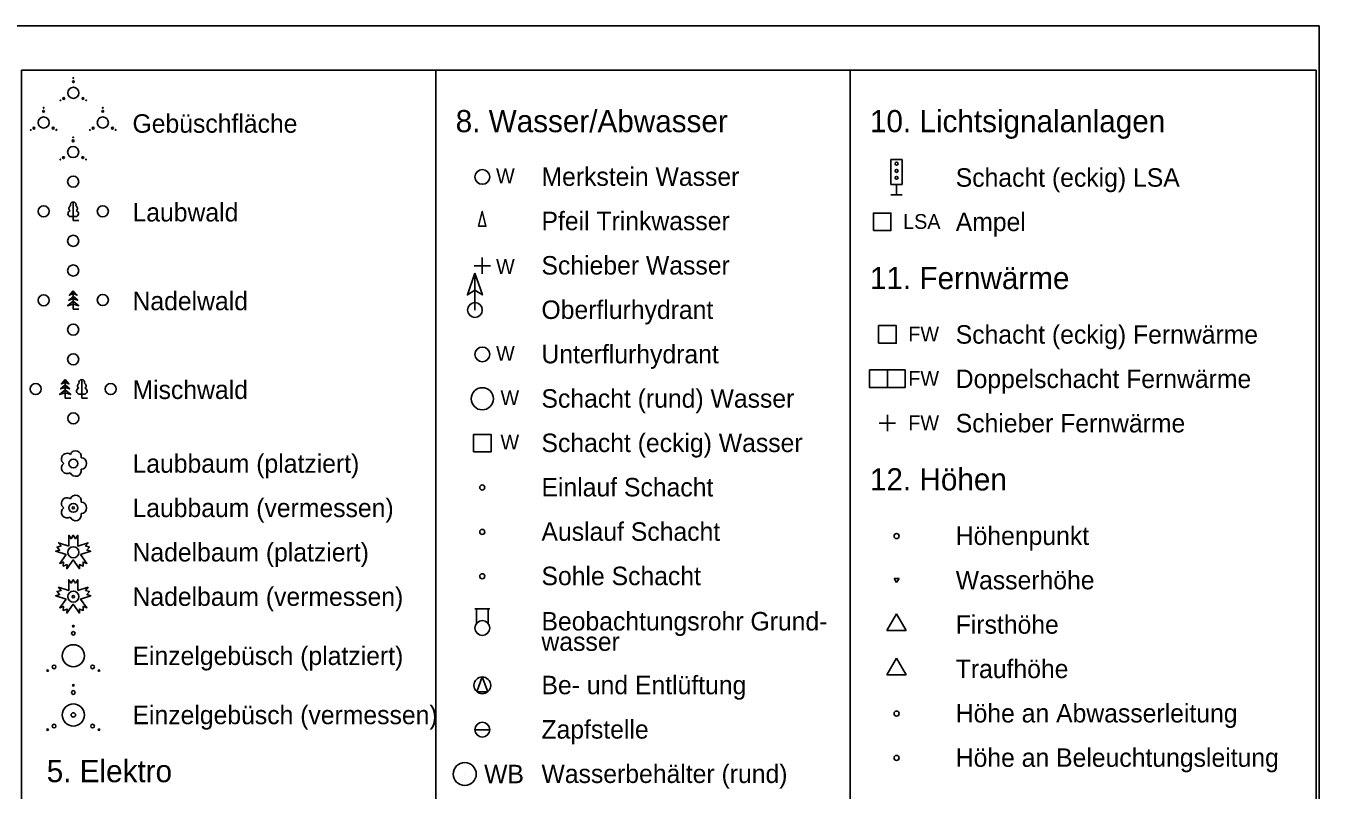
# Model space of a CAD drawing. Extents: x 679244 to 679420, y 5639809 to 5639932.
# Drawn here: x 679332.6 to 679420, y 5639880 to 5639931.7 of the extents above; entities that cross this region are included whole.
import ezdxf

# ---------------------------------------------------------------- set-up
doc = ezdxf.new("R2010")
doc.units = 0
for name, color, linetype in [('Ampel', 7, 'Continuous'), ('Auslauf_schacht', 7, 'Continuous'), ('Be_entlueftung', 7, 'Continuous'), ('Beobrohr_gw', 7, 'Continuous'), ('Busch_platz', 7, 'Continuous'), ('Busch_verm', 7, 'Continuous'), ('Default', 7, 'Continuous'), ('Doppelschacht_fw', 7, 'Continuous'), ('Einlauf_schacht', 7, 'Continuous'), ('Gebuesch', 7, 'Continuous'), ('Hoehe_aw_symbol', 7, 'Continuous'), ('Hoehe_bel_symbol', 7, 'Continuous'), ('Hoehe_first_symbol', 7, 'Continuous'), ('Hoehe_trauf_symbol', 7, 'Continuous'), ('Hoehe_wasser_symbol', 7, 'Continuous'), ('Hoehenpunkt_symbol', 7, 'Continuous'), ('Laubbaum', 7, 'Continuous'), ('Laubwald', 7, 'Continuous'), ('Merkstein_wasser', 7, 'Continuous'), ('Mischwald', 7, 'Continuous'), ('Nadelbaum', 7, 'Continuous'), ('Nadelwald', 7, 'Continuous'), ('Oberflurhydrant', 7, 'Continuous'), ('Pfeil_trinkwasser', 7, 'Continuous'), ('Rahmen_1', 7, 'Continuous'), ('Schacht_e_fw', 7, 'Continuous'), ('Schacht_e_lsa', 7, 'Continuous'), ('Schacht_e_wasser', 7, 'Continuous'), ('Schacht_r_wasser', 7, 'Continuous'), ('Schieber_fw', 7, 'Continuous'), ('Schieber_wasser', 7, 'Continuous'), ('Schrift_fw', 7, 'Continuous'), ('Schrift_lsa', 7, 'Continuous'), ('Schrift_w', 7, 'Continuous'), ('Schrift_wb', 7, 'Continuous'), ('Sohle_schacht', 7, 'Continuous'), ('Unterflurhydrant', 7, 'Continuous'), ('Wasserbehaelter_rund', 7, 'Continuous'), ('Zapfstelle', 7, 'Continuous')]:
    doc.layers.add(name, color=color, linetype=linetype)

msp = doc.modelspace()

# ---------------------------------------------------------------- linework, layer by layer
at = {"layer": 'Ampel'}
for p, q in [((679391.052, 5639922.636), (679391.801, 5639922.636)), ((679391.052, 5639922.636), (679391.052, 5639920.933)), ((679391.801, 5639922.636), (679391.801, 5639920.933)), ((679391.052, 5639920.933), (679391.801, 5639920.933)), ((679391.052, 5639920.233), (679391.801, 5639920.233)), ((679391.427, 5639920.233), (679391.427, 5639920.933))]:
    msp.add_line(p, q, dxfattribs=at)
for centre in [(679391.427, 5639922.347), (679391.427, 5639921.861), (679391.427, 5639921.392)]:
    msp.add_circle(centre, 0.1, dxfattribs=at)
at = {"layer": 'Auslauf_schacht'}
msp.add_circle((679363.427, 5639897.453), 0.171, dxfattribs=at)
at = {"layer": 'Be_entlueftung'}
msp.add_lwpolyline([(679363.794, 5639886.646), (679363.426, 5639887.645), (679363.058, 5639886.647)], close=True, dxfattribs=at)
msp.add_circle((679363.427, 5639887.078), 0.567, dxfattribs=at)
at = {"layer": 'Beobrohr_gw'}
for p, q in [((679362.927, 5639892.255), (679363.927, 5639892.257)), ((679363.03, 5639892.255), (679363.03, 5639891.257)), ((679363.824, 5639892.257), (679363.824, 5639891.257))]:
    msp.add_line(p, q, dxfattribs=at)
msp.add_circle((679363.427, 5639890.953), 0.5, dxfattribs=at)
at = {"layer": 'Busch_platz'}
for centre, radius in [((679335.783, 5639890.595), 0.125), ((679335.783, 5639891.078), 0.05), ((679335.783, 5639889.078), 0.75), ((679334.05, 5639888.077), 0.05), ((679334.479, 5639888.325), 0.125), ((679337.086, 5639888.326), 0.125), ((679337.515, 5639888.078), 0.05)]:
    msp.add_circle(centre, radius, dxfattribs=at)
at = {"layer": 'Busch_verm'}
for centre, radius in [((679335.783, 5639887.078), 0.05), ((679335.783, 5639886.595), 0.125), ((679335.783, 5639885.078), 0.75), ((679335.783, 5639885.078), 0.151), ((679334.479, 5639884.325), 0.125), ((679337.086, 5639884.326), 0.125), ((679334.05, 5639884.077), 0.05), ((679337.515, 5639884.078), 0.05)]:
    msp.add_circle(centre, radius, dxfattribs=at)
at = {"layer": 'Default'}
for points in [[(679332.286, 5639808.666), (679360.286, 5639808.666), (679360.286, 5639928.666), (679332.286, 5639928.666)], [(679360.286, 5639808.666), (679388.286, 5639808.666), (679388.286, 5639928.666), (679360.286, 5639928.666)], [(679388.286, 5639808.666), (679419.79, 5639808.666), (679419.79, 5639928.666), (679388.286, 5639928.666)]]:
    msp.add_lwpolyline(points, close=True, dxfattribs=at)
at = {"layer": 'Doppelschacht_fw'}
for points in [[(679389.609, 5639908.41), (679390.809, 5639908.41), (679390.809, 5639907.21), (679389.609, 5639907.21)], [(679390.809, 5639908.41), (679392.009, 5639908.41), (679392.009, 5639907.21), (679390.809, 5639907.21)]]:
    msp.add_lwpolyline(points, close=True, dxfattribs=at)
at = {"layer": 'Einlauf_schacht'}
msp.add_circle((679363.427, 5639900.453), 0.171, dxfattribs=at)
at = {"layer": 'Gebuesch'}
for centre, radius in [((679335.786, 5639928.136), 0.025), ((679335.786, 5639927.136), 0.375), ((679335.786, 5639927.894), 0.0625), ((679334.92, 5639926.635), 0.025), ((679335.134, 5639926.759), 0.0625), ((679336.438, 5639926.76), 0.0625), ((679336.652, 5639926.636), 0.025), ((679333.774, 5639925.131), 0.375), ((679333.774, 5639925.889), 0.0625), ((679333.774, 5639926.131), 0.025), ((679337.775, 5639925.131), 0.375), ((679337.775, 5639925.889), 0.0625), ((679337.775, 5639926.131), 0.025), ((679332.907, 5639924.63), 0.025), ((679333.122, 5639924.754), 0.0625), ((679334.425, 5639924.755), 0.0625), ((679334.64, 5639924.631), 0.025), ((679336.909, 5639924.63), 0.025), ((679337.123, 5639924.754), 0.0625), ((679338.427, 5639924.755), 0.0625), ((679338.641, 5639924.631), 0.025), ((679335.771, 5639923.892), 0.0625), ((679335.771, 5639924.133), 0.025), ((679335.119, 5639922.757), 0.0625), ((679335.771, 5639923.133), 0.375), ((679336.422, 5639922.757), 0.0625), ((679334.904, 5639922.633), 0.025), ((679336.637, 5639922.633), 0.025)]:
    msp.add_circle(centre, radius, dxfattribs=at)
at = {"layer": 'Hoehe_aw_symbol'}
msp.add_circle((679391.427, 5639885.171), 0.171, dxfattribs=at)
at = {"layer": 'Hoehe_bel_symbol'}
msp.add_circle((679391.427, 5639882.171), 0.171, dxfattribs=at)
at = {"layer": 'Hoehe_first_symbol'}
for p, q in [((679390.777, 5639890.796), (679391.427, 5639891.922)), ((679391.427, 5639891.922), (679392.077, 5639890.796)), ((679392.077, 5639890.796), (679390.777, 5639890.796))]:
    msp.add_line(p, q, dxfattribs=at)
at = {"layer": 'Hoehe_trauf_symbol'}
for p, q in [((679390.777, 5639887.796), (679391.427, 5639888.922)), ((679391.427, 5639888.922), (679392.077, 5639887.796)), ((679392.077, 5639887.796), (679390.777, 5639887.796))]:
    msp.add_line(p, q, dxfattribs=at)
at = {"layer": 'Hoehe_wasser_symbol'}
for p, q in [((679391.429, 5639894.021), (679391.264, 5639894.308)), ((679391.264, 5639894.308), (679391.595, 5639894.308)), ((679391.429, 5639894.021), (679391.595, 5639894.308))]:
    msp.add_line(p, q, dxfattribs=at)
at = {"layer": 'Hoehenpunkt_symbol'}
msp.add_circle((679391.427, 5639897.171), 0.171, dxfattribs=at)
at = {"layer": 'Laubbaum'}
for centre, radius in [((679335.783, 5639902.078), 0.3), ((679335.783, 5639899.078), 0.3), ((679335.783, 5639899.078), 0.075)]:
    msp.add_circle(centre, radius, dxfattribs=at)
for centre, radius, start, end in [((679335.357, 5639902.386), 0.383, 54.09544, 235.24653), ((679335.941, 5639902.554), 0.386, 346.95182, 158.43781), ((679335.361, 5639901.771), 0.381, 126.94043, 303.82011), ((679336.292, 5639902.079), 0.389, 273.64301, 86.35699), ((679335.936, 5639901.6), 0.391, 201.90109, 13.48189), ((679335.357, 5639899.386), 0.383, 54.09544, 235.24653), ((679335.941, 5639899.554), 0.386, 346.95182, 158.43781), ((679336.292, 5639899.079), 0.389, 273.64301, 86.35699), ((679335.361, 5639898.771), 0.381, 126.94043, 303.82011), ((679335.936, 5639898.6), 0.391, 201.90109, 13.48189)]:
    msp.add_arc(centre, radius, start, end, dxfattribs=at)
at = {"layer": 'Laubwald'}
for p, q in [((679335.773, 5639918.767), (679335.773, 5639919.754)), ((679335.603, 5639918.767), (679335.691, 5639918.767)), ((679335.691, 5639918.767), (679335.765, 5639918.767)), ((679335.859, 5639918.767), (679335.765, 5639918.767)), ((679335.765, 5639918.767), (679335.773, 5639918.767)), ((679335.774, 5639918.765), (679335.777, 5639918.507)), ((679335.775, 5639918.506), (679336.15, 5639918.506)), ((679335.947, 5639918.767), (679335.859, 5639918.767))]:
    msp.add_line(p, q, dxfattribs=at)
for centre in [(679335.775, 5639921.131), (679333.775, 5639919.131), (679337.775, 5639919.131), (679335.775, 5639917.131)]:
    msp.add_circle(centre, 0.375, dxfattribs=at)
for centre, radius, start, end in [((679335.677, 5639919.328), 0.191, 115.00316, 235.6561), ((679335.767, 5639919.572), 0.184, 87.40533, 202.50493), ((679335.783, 5639919.572), 0.184, 337.49507, 92.59467), ((679335.873, 5639919.328), 0.191, 304.3439, 64.99684), ((679335.623, 5639918.972), 0.206, 105.02089, 264.45944), ((679335.927, 5639918.972), 0.206, 275.54056, 74.97911)]:
    msp.add_arc(centre, radius, start, end, dxfattribs=at)
at = {"layer": 'Merkstein_wasser'}
msp.add_circle((679363.427, 5639921.453), 0.5, dxfattribs=at)
at = {"layer": 'Mischwald'}
for p, q in [((679335.233, 5639907.753), (679335.233, 5639906.503)), ((679336.356, 5639906.764), (679336.356, 5639907.751)), ((679335.233, 5639906.503), (679335.608, 5639906.503)), ((679336.186, 5639906.764), (679336.274, 5639906.764)), ((679336.274, 5639906.764), (679336.348, 5639906.764)), ((679336.442, 5639906.764), (679336.348, 5639906.764)), ((679336.348, 5639906.764), (679336.356, 5639906.764)), ((679336.357, 5639906.762), (679336.359, 5639906.504)), ((679336.358, 5639906.503), (679336.733, 5639906.503)), ((679336.53, 5639906.764), (679336.442, 5639906.764))]:
    msp.add_line(p, q, dxfattribs=at)
for points in [[(679335.233, 5639907.394), (679334.926, 5639907.117), (679335.233, 5639907.217)], [(679335.233, 5639907.75), (679334.978, 5639907.455), (679335.233, 5639907.558)], [(679335.234, 5639907.75), (679335.489, 5639907.455), (679335.234, 5639907.558)], [(679335.234, 5639907.394), (679335.541, 5639907.117), (679335.234, 5639907.217)], [(679335.233, 5639907.057), (679334.855, 5639906.735), (679335.233, 5639906.847)], [(679335.233, 5639907.057), (679335.611, 5639906.735), (679335.233, 5639906.847)]]:
    msp.add_lwpolyline(points, dxfattribs=at)
for points in [[(679335.234, 5639907.751), (679335.49, 5639907.455), (679335.233, 5639907.559)], [(679335.233, 5639907.395), (679335.542, 5639907.117), (679335.233, 5639907.217)], [(679335.233, 5639907.057), (679335.612, 5639906.736), (679335.234, 5639906.846)]]:
    msp.add_lwpolyline(points, close=True, dxfattribs=at)
for centre in [(679335.775, 5639909.124), (679333.24, 5639907.111), (679338.311, 5639907.111), (679335.783, 5639905.128)]:
    msp.add_circle(centre, 0.375, dxfattribs=at)
for centre, radius, start, end in [((679336.205, 5639906.969), 0.206, 105.02089, 264.45944), ((679336.26, 5639907.326), 0.191, 115.00316, 235.6561), ((679336.349, 5639907.569), 0.184, 87.40533, 202.50493), ((679336.366, 5639907.569), 0.184, 337.49507, 92.59467), ((679336.51, 5639906.969), 0.206, 275.54056, 74.97911), ((679336.455, 5639907.326), 0.191, 304.3439, 64.99684)]:
    msp.add_arc(centre, radius, start, end, dxfattribs=at)
at = {"layer": 'Nadelbaum'}
for points in [[(679336.27, 5639895.914), (679336.7, 5639895.321), (679336.444, 5639895.416), (679336.455, 5639895.142), (679336.2, 5639895.238), (679336.211, 5639894.965), (679335.78, 5639895.558), (679335.35, 5639894.965), (679335.362, 5639895.238), (679335.106, 5639895.142), (679335.117, 5639895.416), (679334.861, 5639895.321), (679335.291, 5639895.914), (679334.594, 5639896.14), (679334.858, 5639896.214), (679334.688, 5639896.428), (679334.951, 5639896.502), (679334.782, 5639896.715), (679335.477, 5639896.49)], [(679335.477, 5639896.49), (679335.477, 5639897.221), (679335.629, 5639896.994), (679335.779, 5639897.221), (679335.931, 5639896.994), (679336.082, 5639897.221), (679336.082, 5639896.49), (679336.779, 5639896.715), (679336.609, 5639896.502), (679336.873, 5639896.429), (679336.703, 5639896.215), (679336.965, 5639896.141), (679336.27, 5639895.914)], [(679335.291, 5639892.914), (679334.594, 5639893.14), (679334.858, 5639893.214), (679334.688, 5639893.428), (679334.951, 5639893.502), (679334.782, 5639893.715), (679335.477, 5639893.49), (679335.477, 5639894.221), (679335.629, 5639893.994), (679335.779, 5639894.221), (679335.931, 5639893.994), (679336.082, 5639894.221), (679336.082, 5639893.49)], [(679336.082, 5639893.49), (679336.779, 5639893.715), (679336.609, 5639893.502), (679336.873, 5639893.429), (679336.703, 5639893.215), (679336.965, 5639893.141), (679336.27, 5639892.914), (679336.7, 5639892.321), (679336.444, 5639892.416), (679336.455, 5639892.142), (679336.2, 5639892.238), (679336.211, 5639891.965), (679335.78, 5639892.558), (679335.35, 5639891.965), (679335.362, 5639892.238), (679335.106, 5639892.142), (679335.117, 5639892.416), (679334.861, 5639892.321), (679335.291, 5639892.914)]]:
    msp.add_lwpolyline(points, dxfattribs=at)
for centre, radius in [((679335.783, 5639896.078), 0.375), ((679335.783, 5639893.078), 0.375), ((679335.783, 5639893.078), 0.075)]:
    msp.add_circle(centre, radius, dxfattribs=at)
at = {"layer": 'Nadelwald'}
for p, q in [((679335.775, 5639913.756), (679335.775, 5639912.506)), ((679335.775, 5639912.506), (679336.15, 5639912.506))]:
    msp.add_line(p, q, dxfattribs=at)
for points in [[(679335.775, 5639913.396), (679335.469, 5639913.119), (679335.775, 5639913.219)], [(679335.775, 5639913.753), (679335.52, 5639913.457), (679335.775, 5639913.561)], [(679335.777, 5639913.753), (679336.032, 5639913.457), (679335.777, 5639913.561)], [(679335.777, 5639913.396), (679336.083, 5639913.119), (679335.777, 5639913.219)], [(679335.775, 5639913.06), (679335.397, 5639912.738), (679335.775, 5639912.849)], [(679335.776, 5639913.06), (679336.154, 5639912.738), (679335.776, 5639912.849)]]:
    msp.add_lwpolyline(points, dxfattribs=at)
for points in [[(679335.776, 5639913.754), (679336.032, 5639913.457), (679335.776, 5639913.562)], [(679335.776, 5639913.397), (679336.084, 5639913.119), (679335.776, 5639913.22)], [(679335.776, 5639913.06), (679336.155, 5639912.738), (679335.776, 5639912.849)]]:
    msp.add_lwpolyline(points, close=True, dxfattribs=at)
for centre in [(679335.775, 5639915.124), (679333.782, 5639913.113), (679337.775, 5639913.131), (679335.775, 5639911.131)]:
    msp.add_circle(centre, 0.375, dxfattribs=at)
at = {"layer": 'Oberflurhydrant'}
msp.add_line((679362.927, 5639912.453), (679362.927, 5639914.947), dxfattribs=at)
msp.add_lwpolyline([(679362.927, 5639914.94), (679362.417, 5639913.473), (679362.927, 5639913.796), (679363.433, 5639913.477)], close=True, dxfattribs=at)
msp.add_circle((679362.927, 5639912.453), 0.5, dxfattribs=at)
at = {"layer": 'Pfeil_trinkwasser'}
msp.add_lwpolyline([(679363.177, 5639918.119), (679363.427, 5639919.119), (679363.677, 5639918.119)], close=True, dxfattribs=at)
at = {"layer": 'Rahmen_1'}
msp.add_lwpolyline([(679419.991, 5639808.515), (679243.507, 5639808.515), (679243.507, 5639931.667), (679419.991, 5639931.667)], close=True, dxfattribs=at)
at = {"layer": 'Schacht_e_fw'}
msp.add_lwpolyline([(679390.215, 5639910.21), (679391.403, 5639910.21), (679391.403, 5639911.398), (679390.215, 5639911.398)], close=True, dxfattribs=at)
at = {"layer": 'Schacht_e_lsa'}
msp.add_lwpolyline([(679389.864, 5639917.821), (679391.052, 5639917.821), (679391.052, 5639919.009), (679389.864, 5639919.009)], close=True, dxfattribs=at)
at = {"layer": 'Schacht_e_wasser'}
msp.add_lwpolyline([(679362.833, 5639902.859), (679364.021, 5639902.859), (679364.021, 5639904.047), (679362.833, 5639904.047)], close=True, dxfattribs=at)
at = {"layer": 'Schacht_r_wasser'}
msp.add_circle((679363.427, 5639906.453), 0.75, dxfattribs=at)
at = {"layer": 'Schieber_fw'}
for q in [(679390.809, 5639905.359), (679390.26, 5639904.81), (679390.809, 5639904.261), (679391.358, 5639904.81)]:
    msp.add_line((679390.809, 5639904.81), q, dxfattribs=at)
at = {"layer": 'Schieber_wasser'}
for q in [(679363.427, 5639916.002), (679362.878, 5639915.453), (679363.427, 5639914.904), (679363.976, 5639915.453)]:
    msp.add_line((679363.427, 5639915.453), q, dxfattribs=at)
at = {"layer": 'Sohle_schacht'}
msp.add_circle((679363.427, 5639894.453), 0.171, dxfattribs=at)
at = {"layer": 'Unterflurhydrant'}
msp.add_circle((679363.427, 5639909.453), 0.5, dxfattribs=at)
at = {"layer": 'Wasserbehaelter_rund'}
msp.add_line((679362.242, 5639881.078), (679362.242, 5639881.078), dxfattribs=at)
msp.add_circle((679362.242, 5639881.078), 0.775, dxfattribs=at)
at = {"layer": 'Zapfstelle'}
msp.add_line((679362.927, 5639884.078), (679363.927, 5639884.077), dxfattribs=at)
msp.add_circle((679363.426, 5639884.078), 0.5, dxfattribs=at)
msp.add_arc((679363.426, 5639884.078), 0.5, 179.89068, 359.87601, dxfattribs=at)

# ---------------------------------------------------------------- texts
at = {"layer": 'Default'}
for s, height, p in [('Gebüschfläche', 1.25, (679339.783, 5639924.44)), ('8. Wasser/Abwasser', 1.5, (679361.628, 5639924.477)), ('10. Lichtsignalanlagen', 1.5, (679389.628, 5639924.477)), ('Merkstein Wasser', 1.25, (679367.427, 5639920.851)), ('Schacht (eckig) LSA', 1.25, (679395.427, 5639920.79)), ('Laubwald', 1.25, (679339.783, 5639918.44)), ('Pfeil Trinkwasser', 1.25, (679367.427, 5639917.851)), ('Ampel', 1.25, (679395.427, 5639917.79)), ('Schieber Wasser', 1.25, (679367.427, 5639914.851)), ('11. Fernwärme', 1.5, (679389.628, 5639913.867)), ('Nadelwald', 1.25, (679339.783, 5639912.44)), ('Oberflurhydrant', 1.25, (679367.427, 5639911.851)), ('Schacht (eckig) Fernwärme', 1.25, (679395.427, 5639910.179)), ('Unterflurhydrant', 1.25, (679367.427, 5639908.851)), ('Doppelschacht Fernwärme', 1.25, (679395.427, 5639907.179)), ('Mischwald', 1.25, (679339.783, 5639906.44)), ('Schacht (rund) Wasser', 1.25, (679367.427, 5639905.851)), ('Schieber Fernwärme', 1.25, (679395.427, 5639904.179)), ('Schacht (eckig) Wasser', 1.25, (679367.427, 5639902.851)), ('Laubbaum (platziert)', 1.25, (679339.783, 5639901.453)), ('12. Höhen', 1.5, (679389.628, 5639900.256)), ('Einlauf Schacht', 1.25, (679367.427, 5639899.851)), ('Laubbaum (vermessen)', 1.25, (679339.783, 5639898.453)), ('Auslauf Schacht', 1.25, (679367.427, 5639896.851)), ('Höhenpunkt', 1.25, (679395.427, 5639896.569)), ('Nadelbaum (platziert)', 1.25, (679339.783, 5639895.453)), ('Sohle Schacht', 1.25, (679367.427, 5639893.851)), ('Wasserhöhe', 1.25, (679395.427, 5639893.569)), ('Nadelbaum (vermessen)', 1.25, (679339.783, 5639892.453)), ('Beobachtungsrohr Grund-', 1.25, (679367.427, 5639890.788)), ('Firsthöhe', 1.25, (679395.427, 5639890.569)), ('Einzelgebüsch (platziert)', 1.25, (679339.783, 5639888.453)), ('wasser', 1.25, (679367.427, 5639889.413)), ('Traufhöhe', 1.25, (679395.427, 5639887.569)), ('Be- und Entlüftung', 1.25, (679367.427, 5639886.476)), ('Einzelgebüsch (vermessen)', 1.25, (679339.783, 5639884.453)), ('Höhe an Abwasserleitung', 1.25, (679395.427, 5639884.569)), ('Zapfstelle', 1.25, (679367.427, 5639883.476)), ('Höhe an Beleuchtungsleitung', 1.25, (679395.427, 5639881.569)), ('5. Elektro', 1.5, (679333.984, 5639880.53)), ('Wasserbehälter (rund)', 1.25, (679367.427, 5639880.476))]:
    msp.add_text(s, height=height, dxfattribs=at).set_placement(p)
at = {"layer": 'Schrift_fw'}
for p in [(679392.222, 5639910.33), (679392.222, 5639907.33), (679392.222, 5639904.33)]:
    msp.add_text('FW', height=1, dxfattribs=at).set_placement(p)
at = {"layer": 'Schrift_lsa'}
msp.add_text('LSA', height=1, dxfattribs=at).set_placement((679391.871, 5639917.94))
at = {"layer": 'Schrift_w'}
for p in [(679364.357, 5639921.026), (679364.357, 5639914.901), (679364.357, 5639909.026), (679364.657, 5639906.026), (679364.657, 5639903.026)]:
    msp.add_text('W', height=1, dxfattribs=at).set_placement(p)
at = {"layer": 'Schrift_wb'}
msp.add_text('WB', height=1.249, dxfattribs=at).set_placement((679363.55, 5639880.458))

doc.saveas('drawing.dxf')
